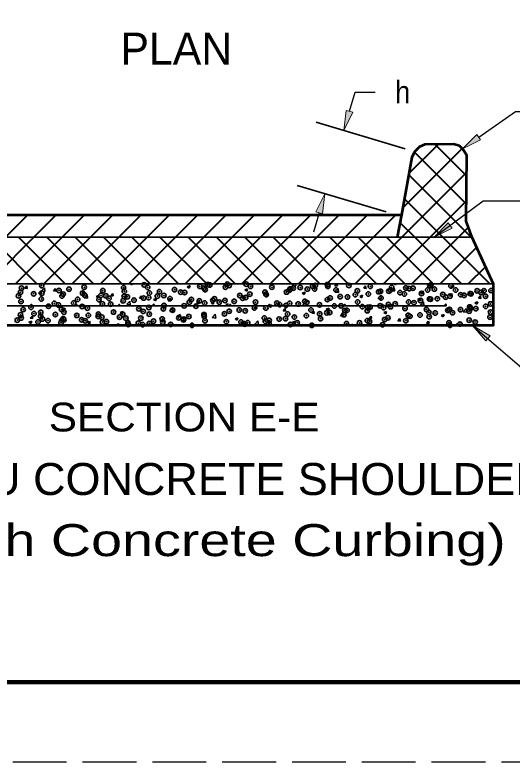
# Model space of a CAD drawing. Extents: x 14 to 49.3, y 28 to 50.
# Drawn here: x 19.642 to 22.747, y 28.044 to 32.715 of the extents above; entities that cross this region are included whole.
import ezdxf

# ---------------------------------------------------------------- set-up
doc = ezdxf.new("R2010")
doc.units = 0
doc.header["$LTSCALE"] = 0.056
doc.header["$PDMODE"] = 32
doc.header["$PDSIZE"] = 0.028
doc.linetypes.add('LONG_DASHED', pattern=[7.5, 6, -1.5])
for name, color, linetype, lineweight in [('1', 7, 'Continuous', 35), ('3', 7, 'Continuous', 13), ('6', 7, 'Continuous', 13)]:
    doc.layers.add(name, color=color, linetype=linetype, lineweight=lineweight)

msp = doc.modelspace()

# ---------------------------------------------------------------- hatches: boundary and pattern name
at = {"layer": '1'}
for points in [[(21.7515, 32.10658), (21.71158, 32.1185), (21.69583, 31.99283), (21.69583, 31.99283)], [(21.56208, 31.47158), (21.52217, 31.4835), (21.57783, 31.59733), (21.57783, 31.59733)]]:
    msp.add_hatch(color=256, dxfattribs=at).paths.add_polyline_path(points)
at = {"layer": '3'}
for points in [[(22.55058, 31.93375), (22.52658, 31.96783), (22.43642, 31.87883), (22.43642, 31.87883)], [(22.373, 31.38267), (22.34825, 31.41617), (22.25983, 31.3255), (22.25983, 31.3255)], [(22.58267, 30.67767), (22.60933, 30.70967), (22.49992, 30.77358), (22.49992, 30.77358)]]:
    msp.add_hatch(color=256, dxfattribs=at).paths.add_polyline_path(points)

# ---------------------------------------------------------------- linework, layer by layer
at = {"layer": '1', "lineweight": 25}
for p, q in [((21.7315, 32.11258), (21.76725, 32.23233)), ((21.76725, 32.23233), (21.89225, 32.23233)), ((21.54208, 31.4775), (21.50633, 31.35775))]:
    msp.add_line(p, q, dxfattribs=at)
at = {"layer": '1'}
for p, q in [((22.07942, 31.87833), (21.52333, 32.04425)), ((21.96142, 31.48292), (21.40533, 31.64875)), ((18.97608, 31.3255), (22.03233, 31.3255)), ((22.03233, 31.3255), (22.4955, 31.3255)), ((18.93983, 31.03367), (22.62858, 31.03367)), ((19.70317, 31.00633), (19.71517, 31.02075)), ((19.71808, 31.00508), (19.71517, 31.02075)), ((20.36208, 31.03367), (20.3715, 31.02733)), ((20.3715, 31.02733), (20.37358, 31.03367)), ((20.71833, 31.01567), (20.73583, 31.02242)), ((20.71833, 31.01567), (20.73075, 31.00725)), ((20.73075, 31.00725), (20.73583, 31.02242)), ((21.37417, 31.02517), (21.38225, 31.03367)), ((21.37417, 31.02517), (21.39642, 31.02175)), ((21.39642, 31.02175), (21.395, 31.03367)), ((21.64092, 31.02183), (21.65083, 31.03367)), ((21.64092, 31.02183), (21.65583, 31.0205)), ((21.65583, 31.0205), (21.65342, 31.03367)), ((21.82025, 31.00617), (21.83225, 31.0205)), ((21.83517, 31.00483), (21.83225, 31.0205)), ((22.01008, 31.03367), (22.01867, 31.02783)), ((22.01867, 31.02783), (22.02058, 31.03367)), ((22.3655, 31.01625), (22.383, 31.02292)), ((22.3655, 31.01625), (22.37792, 31.00783)), ((22.378, 31.00783), (22.383, 31.02292)), ((19.70317, 31.00633), (19.71808, 31.00508)), ((19.78975, 30.97508), (19.80725, 30.98183)), ((19.78975, 30.97508), (19.80217, 30.96667)), ((19.80217, 30.96667), (19.80725, 30.98183)), ((19.80642, 30.98858), (19.82592, 31.00883)), ((19.80642, 30.98858), (19.82867, 30.98508)), ((19.82867, 30.98508), (19.82592, 31.00883)), ((19.8825, 30.99067), (19.8945, 31.005)), ((19.8825, 30.99067), (19.89742, 30.98933)), ((19.89742, 30.98933), (19.8945, 31.005)), ((20.06175, 30.975), (20.07383, 30.98933)), ((20.06175, 30.975), (20.07675, 30.97367)), ((20.07675, 30.97367), (20.07383, 30.98933)), ((20.24108, 30.95933), (20.25317, 30.97367)), ((20.256, 30.958), (20.25317, 30.97367)), ((21.07758, 30.99567), (21.09508, 31.00233)), ((21.07758, 30.99567), (21.09008, 30.98725)), ((21.09008, 30.98725), (21.09517, 31.00233)), ((21.43692, 30.97558), (21.45442, 30.98233)), ((21.43692, 30.97558), (21.44933, 30.96725)), ((21.44933, 30.96725), (21.45442, 30.98233)), ((21.641, 30.98383), (21.66042, 31.00408)), ((21.641, 30.98383), (21.66325, 30.98033)), ((21.66325, 30.98033), (21.66042, 31.00408)), ((21.82025, 31.00617), (21.83517, 31.00483)), ((21.99958, 30.9905), (22.01158, 31.00483)), ((21.99958, 30.9905), (22.0145, 30.98917)), ((22.0145, 30.98917), (22.01158, 31.00483)), ((22.17883, 30.97475), (22.19092, 30.98917)), ((22.17883, 30.97475), (22.19383, 30.9735)), ((22.19383, 30.9735), (22.19092, 30.98917)), ((22.35817, 30.95908), (22.37025, 30.97342)), ((22.37317, 30.95775), (22.37025, 30.97342)), ((20.07325, 30.94717), (20.09275, 30.9675)), ((20.07325, 30.94717), (20.0955, 30.94375)), ((20.0955, 30.94375), (20.09275, 30.9675)), ((20.149, 30.95508), (20.1665, 30.96175)), ((20.149, 30.95508), (20.16142, 30.94667)), ((20.16142, 30.94667), (20.1665, 30.96175)), ((20.24108, 30.95933), (20.256, 30.958)), ((20.34008, 30.90583), (20.35958, 30.92608)), ((20.36233, 30.90233), (20.35958, 30.92608)), ((20.42042, 30.94358), (20.43242, 30.958)), ((20.42042, 30.94358), (20.43533, 30.94233)), ((20.43533, 30.94233), (20.4325, 30.958)), ((20.50825, 30.935), (20.52575, 30.94175)), ((20.50825, 30.935), (20.52075, 30.92667)), ((20.52075, 30.92667), (20.52575, 30.94175)), ((20.59975, 30.92792), (20.61175, 30.94225)), ((20.59975, 30.92792), (20.61467, 30.92658)), ((20.61467, 30.92658), (20.61175, 30.94225)), ((20.779, 30.91225), (20.79108, 30.92658)), ((20.794, 30.91092), (20.79108, 30.92658)), ((21.79617, 30.95558), (21.81367, 30.96233)), ((21.79617, 30.95558), (21.80858, 30.94725)), ((21.80858, 30.94725), (21.81367, 30.96233)), ((21.90783, 30.94242), (21.92725, 30.96275)), ((21.90783, 30.94242), (21.93, 30.939)), ((21.93, 30.939), (21.92725, 30.96275)), ((22.1555, 30.93558), (22.173, 30.94233)), ((22.1555, 30.93558), (22.173, 30.94233)), ((22.1555, 30.93558), (22.16792, 30.92717)), ((22.16792, 30.92717), (22.173, 30.94233)), ((22.35817, 30.95908), (22.37308, 30.95775)), ((22.51475, 30.91558), (22.53225, 30.92225)), ((22.52717, 30.90717), (22.53225, 30.92225)), ((22.5375, 30.94342), (22.54958, 30.95775)), ((22.5375, 30.94342), (22.55242, 30.94208)), ((22.55242, 30.94208), (22.54958, 30.95775)), ((18.88533, 30.89658), (22.33242, 30.89658)), ((19.93892, 30.87442), (19.95642, 30.88117)), ((19.95142, 30.866), (19.95642, 30.88117)), ((20.34008, 30.90583), (20.36233, 30.90233)), ((20.60692, 30.86442), (20.62633, 30.88475)), ((20.62908, 30.861), (20.62633, 30.88475)), ((20.779, 30.91225), (20.794, 30.91092)), ((20.86758, 30.915), (20.88508, 30.92175)), ((20.86758, 30.915), (20.88, 30.90667)), ((20.88, 30.90658), (20.88508, 30.92175)), ((20.95833, 30.89658), (20.97042, 30.91092)), ((20.95833, 30.89658), (20.97325, 30.89525)), ((20.97333, 30.89525), (20.97042, 30.91092)), ((21.13767, 30.88083), (21.14975, 30.89525)), ((21.13767, 30.88083), (21.15258, 30.87958)), ((21.15258, 30.87958), (21.14975, 30.89525)), ((21.22683, 30.895), (21.24433, 30.90175)), ((21.22683, 30.895), (21.23925, 30.88658)), ((21.23925, 30.88658), (21.24433, 30.90167)), ((21.317, 30.86517), (21.329, 30.8795)), ((21.33192, 30.86383), (21.329, 30.8795)), ((21.58617, 30.875), (21.60367, 30.88167)), ((21.59858, 30.86658), (21.60367, 30.88167)), ((22.17458, 30.90108), (22.19408, 30.92133)), ((22.17458, 30.90108), (22.19683, 30.89758)), ((22.19683, 30.89758), (22.19408, 30.92133)), ((22.44142, 30.85967), (22.46092, 30.88)), ((22.46367, 30.85625), (22.46092, 30.88)), ((22.51475, 30.91558), (22.52717, 30.90717)), ((19.73783, 30.81833), (19.74992, 30.83267)), ((19.75275, 30.817), (19.74992, 30.83267)), ((19.93892, 30.87442), (19.95142, 30.866)), ((20.29825, 30.85442), (20.31575, 30.86108)), ((20.29825, 30.85442), (20.31067, 30.846)), ((20.31067, 30.846), (20.31575, 30.86108)), ((20.60692, 30.86442), (20.62908, 30.861)), ((20.6575, 30.83442), (20.675, 30.84108)), ((20.6575, 30.83442), (20.66992, 30.826)), ((20.66992, 30.826), (20.675, 30.84108)), ((20.87367, 30.82308), (20.89317, 30.84333)), ((20.89592, 30.81958), (20.89317, 30.84333)), ((21.317, 30.86517), (21.33192, 30.86383)), ((21.49633, 30.8495), (21.50833, 30.86383)), ((21.49633, 30.8495), (21.51125, 30.84817)), ((21.51125, 30.84817), (21.50833, 30.86383)), ((21.58617, 30.875), (21.59858, 30.86658)), ((21.67558, 30.83383), (21.68767, 30.84817)), ((21.67558, 30.83383), (21.69058, 30.8325)), ((21.69058, 30.8325), (21.68767, 30.84817)), ((21.85492, 30.81808), (21.867, 30.8325)), ((21.86983, 30.81683), (21.867, 30.8325)), ((21.94542, 30.85492), (21.96292, 30.86167)), ((21.94542, 30.85492), (21.95783, 30.84658)), ((21.95783, 30.84658), (21.96292, 30.86167)), ((22.30467, 30.83492), (22.32217, 30.84167)), ((22.30467, 30.83492), (22.31717, 30.8265)), ((22.31717, 30.8265), (22.32217, 30.84167)), ((22.44142, 30.85967), (22.46367, 30.85625)), ((19.72892, 30.79383), (19.74642, 30.8005)), ((19.72892, 30.79383), (19.74133, 30.78542)), ((19.73783, 30.81833), (19.75275, 30.817)), ((19.74133, 30.78542), (19.74642, 30.8005)), ((19.74133, 30.78542), (19.74642, 30.8005)), ((19.91717, 30.80267), (19.92917, 30.817)), ((19.91717, 30.80267), (19.93208, 30.80133)), ((19.93208, 30.80133), (19.92917, 30.817)), ((20.0965, 30.78692), (20.1085, 30.80133)), ((20.0965, 30.78692), (20.11142, 30.78567)), ((20.11142, 30.78567), (20.1085, 30.80133)), ((20.27767, 30.77358), (20.28783, 30.78558)), ((20.29008, 30.77358), (20.28783, 30.78558)), ((20.87367, 30.82308), (20.89592, 30.81958)), ((21.01675, 30.81433), (21.03433, 30.82108)), ((21.01675, 30.81433), (21.02925, 30.806)), ((21.02925, 30.806), (21.03433, 30.82108)), ((21.1405, 30.78167), (21.16, 30.802)), ((21.16275, 30.77825), (21.16, 30.802)), ((21.37608, 30.79433), (21.39358, 30.80108)), ((21.37608, 30.79433), (21.3885, 30.78592)), ((21.3885, 30.78592), (21.39358, 30.80108)), ((21.85492, 30.81808), (21.86983, 30.81683)), ((22.03425, 30.80242), (22.04625, 30.81675)), ((22.03425, 30.80242), (22.04917, 30.80108)), ((22.04917, 30.80108), (22.04633, 30.81675)), ((22.21358, 30.78675), (22.22558, 30.80108)), ((22.21358, 30.78675), (22.2285, 30.78542)), ((22.2285, 30.78542), (22.22558, 30.80108)), ((22.2285, 30.78542), (22.22558, 30.80108)), ((22.395, 30.77358), (22.40492, 30.78542)), ((22.40708, 30.77358), (22.40492, 30.78542)), ((20.08817, 30.77375), (20.10567, 30.7805)), ((20.08817, 30.77375), (20.0885, 30.77358)), ((20.10333, 30.77358), (20.10567, 30.7805)), ((21.1405, 30.78167), (21.16275, 30.77825)), ((21.73533, 30.77433), (21.75283, 30.781)), ((21.73533, 30.77433), (21.7365, 30.77358)), ((21.75033, 30.77358), (21.75283, 30.781))]:
    msp.add_line(p, q, dxfattribs=at)
at = {"layer": '1', "lineweight": 40}
for p, q in [((22.10467, 31.72517), (22.287, 31.9075)), ((22.46117, 31.71025), (22.26408, 31.90725)), ((22.06567, 31.50933), (22.43575, 31.87942)), ((22.45975, 31.53483), (22.13758, 31.857)), ((22.0585, 31.3255), (22.46133, 31.72825)), ((22.49233, 31.3255), (22.10283, 31.715)), ((22.31558, 31.3255), (22.07575, 31.56533)), ((22.23533, 31.3255), (22.45992, 31.55008)), ((19.58367, 31.3255), (19.72325, 31.465)), ((19.76042, 31.3255), (19.9, 31.465)), ((19.93725, 31.3255), (20.07675, 31.465)), ((20.114, 31.3255), (20.25358, 31.465)), ((20.29075, 31.3255), (20.43033, 31.465)), ((20.46758, 31.3255), (20.60708, 31.465)), ((20.64433, 31.3255), (20.78392, 31.465)), ((20.82108, 31.3255), (20.96067, 31.465)), ((20.99792, 31.3255), (21.13742, 31.465)), ((21.17467, 31.3255), (21.31425, 31.465)), ((21.35142, 31.3255), (21.491, 31.465)), ((21.52817, 31.3255), (21.66775, 31.465)), ((21.705, 31.3255), (21.84458, 31.465)), ((21.88175, 31.3255), (22.02133, 31.465)), ((22.13883, 31.3255), (22.04867, 31.41558)), ((22.41208, 31.3255), (22.47292, 31.38625)), ((19.46858, 31.03367), (19.76042, 31.3255)), ((19.779, 31.03367), (19.48717, 31.3255)), ((19.64542, 31.03367), (19.93725, 31.3255)), ((19.95575, 31.03367), (19.66392, 31.3255)), ((19.82217, 31.03367), (20.114, 31.3255)), ((20.1325, 31.03367), (19.84067, 31.3255)), ((19.99892, 31.03367), (20.29075, 31.3255)), ((20.30933, 31.03367), (20.0175, 31.3255)), ((20.17575, 31.03367), (20.46758, 31.3255)), ((20.48608, 31.03367), (20.19425, 31.3255)), ((20.3525, 31.03367), (20.64433, 31.3255)), ((20.66283, 31.03367), (20.371, 31.3255)), ((20.52925, 31.03367), (20.82108, 31.3255)), ((20.83967, 31.03367), (20.54783, 31.3255)), ((20.70608, 31.03367), (20.99792, 31.3255)), ((21.01642, 31.03367), (20.72458, 31.3255)), ((20.88283, 31.03367), (21.17467, 31.3255)), ((21.19317, 31.03367), (20.90133, 31.3255)), ((21.05958, 31.03367), (21.35142, 31.3255)), ((21.37, 31.03367), (21.07817, 31.3255)), ((21.23642, 31.03367), (21.52817, 31.3255)), ((21.54675, 31.03367), (21.25492, 31.3255)), ((21.41317, 31.03367), (21.705, 31.3255)), ((21.7235, 31.03367), (21.43167, 31.3255)), ((21.58992, 31.03367), (21.88175, 31.3255)), ((21.90033, 31.03367), (21.6085, 31.3255)), ((21.76675, 31.03367), (22.0585, 31.3255)), ((22.07708, 31.03367), (21.78525, 31.3255)), ((21.9435, 31.03367), (22.23533, 31.3255)), ((22.25383, 31.03367), (21.962, 31.3255)), ((22.12025, 31.03367), (22.41208, 31.3255)), ((22.43058, 31.03367), (22.13883, 31.3255)), ((22.60742, 31.03367), (22.31558, 31.3255)), ((22.49817, 31.31967), (22.49233, 31.3255)), ((22.29708, 31.03367), (22.52475, 31.26133)), ((22.47383, 31.03367), (22.58008, 31.13992))]:
    msp.add_line(p, q, dxfattribs=at)
at = {"layer": '1', "lineweight": 53}
for p, q in [((18.95792, 31.465), (22.05758, 31.465)), ((22.03233, 31.3255), (22.05758, 31.465)), ((22.4955, 31.3255), (22.62858, 31.03367))]:
    msp.add_line(p, q, dxfattribs=at)
at = {"layer": '1', "linetype": 'LONG_DASHED', "lineweight": 25}
msp.add_line((49.17658, 28.04392), (13.97658, 28.04392), dxfattribs=at)
at = {"layer": '1', "lineweight": 158}
msp.add_lwpolyline([(49.09325, 49.54392), (49.09325, 28.54392), (16.59325, 28.54392)], dxfattribs=at)
at = {"layer": '1', "lineweight": 13}
for points in [[(21.7515, 32.10658), (21.71158, 32.1185), (21.69583, 31.99283), (21.69583, 31.99283)], [(21.56208, 31.47158), (21.52217, 31.4835), (21.57783, 31.59733), (21.57783, 31.59733)]]:
    msp.add_lwpolyline(points, close=True, dxfattribs=at)
at = {"layer": '1', "lineweight": 53}
for points in [[(22.05758, 31.465), (22.123, 31.82633), (22.13925, 31.8605), (22.17025, 31.893), (22.2045, 31.90667), (22.38392, 31.90842), (22.4165, 31.89817), (22.43933, 31.87592), (22.46217, 31.84), (22.45892, 31.42608), (22.49525, 31.32258)], [(22.62858, 31.03367), (22.62858, 30.77358), (18.92167, 30.77358), (18.90958, 30.86875), (18.88533, 30.88775), (18.88533, 30.93217), (18.90958, 30.9575), (18.92167, 30.99558), (18.93983, 31.03367)]]:
    msp.add_lwpolyline(points, dxfattribs=at)
at = {"layer": '1', "lineweight": 40}
for centre, radius, start, end in [((19.74483, 30.90133), 0.00308, 0, 180), ((19.74483, 30.90133), 0.00308, 180, 0), ((20.02533, 30.90133), 0.00308, 0, 180), ((20.02533, 30.90133), 0.00308, 180, 0), ((20.29208, 30.90133), 0.00308, 0, 180), ((20.29208, 30.90133), 0.00308, 180, 0), ((20.50825, 30.90133), 0.00308, 0, 180), ((20.50825, 30.90133), 0.00308, 180, 0), ((20.76525, 30.90133), 0.00304, 0, 180), ((20.76525, 30.90133), 0.00304, 180, 0), ((20.98558, 30.90133), 0.00308, 0, 180), ((20.98558, 30.90133), 0.00308, 180, 0), ((21.2295, 30.90133), 0.00308, 0, 180), ((21.2295, 30.90133), 0.00308, 180, 0), ((21.445, 30.90133), 0.00304, 0, 180), ((21.445, 30.90133), 0.00304, 180, 0), ((21.70292, 30.90133), 0.00304, 0, 180), ((21.70292, 30.90133), 0.00304, 180, 0), ((21.93675, 30.90133), 0.00308, 0, 180), ((21.93675, 30.90133), 0.00308, 180, 0), ((22.18025, 30.90133), 0.00304, 0, 180), ((22.18025, 30.90133), 0.00304, 180, 0), ((22.33225, 30.90133), 0.00304, 0, 180), ((22.33225, 30.90133), 0.00304, 180, 0)]:
    msp.add_arc(centre, radius, start, end, dxfattribs=at)
at = {"layer": '1'}
for p in [(19.68292, 31.00642), (19.80917, 31.02242), (20.07425, 31.01292), (20.3205, 31.01025), (20.44883, 31.02792), (20.47117, 31.01175), (20.79667, 31.01808), (20.82267, 31.00692), (20.84633, 31.02942), (20.85925, 31.02625), (20.9565, 31.013), (20.96842, 31.03192), (20.97975, 31.02375), (21.08642, 31.03175), (21.11325, 31.01808), (21.24667, 31.0125), (21.36125, 31.00242), (21.38017, 31.00683), (21.42383, 31.01067), (21.50133, 31.0195), (21.5185, 31.02317), (21.59433, 31.02917), (21.59617, 31.0185), (21.72783, 31.0235), (21.86125, 31.01783), (21.99475, 31.01225), (22.08308, 31.0075), (22.10392, 31.00358), (22.12817, 31.00658), (22.23375, 31.02233), (22.24092, 31.02833), (22.36575, 31.0205), (19.66442, 30.95892), (19.67625, 30.981), (19.75908, 30.97142), (19.80967, 30.97533), (19.917, 30.99217), (19.936, 30.95792), (19.94317, 30.96975), (19.97958, 31.00042), (20.06433, 30.9755), (20.07658, 30.96408), (20.17958, 30.96167), (20.19058, 30.9915), (20.21008, 30.95842), (20.32367, 30.95575), (20.32533, 30.98675), (20.48158, 30.97658), (20.53108, 30.95683), (20.54417, 30.98483), (20.57208, 30.96067), (20.63883, 30.99725), (20.67683, 30.98183), (20.70192, 30.97942), (20.83025, 30.997), (21.04608, 30.96092), (21.10867, 30.96917), (21.20333, 30.98167), (21.20975, 30.9695), (21.21167, 30.96617), (21.338, 30.98217), (21.3555, 30.9945), (21.46783, 31.00092), (21.51358, 31.00117), (21.64708, 30.99558), (21.76792, 30.966), (21.7805, 30.98992), (21.84925, 30.97), (21.914, 30.98425), (21.92575, 30.98683), (21.97767, 30.98758), (21.98833, 30.99508), (22.04742, 30.97867), (22.07417, 30.97042), (22.18092, 30.973), (22.22, 30.9955), (22.26167, 31.00092), (22.31433, 30.96733), (22.35908, 30.95675), (22.39508, 30.99533), (22.42567, 30.96558), (22.44783, 30.96175), (22.48533, 30.97275), (22.49033, 30.97117), (22.5285, 30.98967), (22.55292, 30.97942), (22.5715, 30.99067), (22.58125, 30.95608), (22.61517, 30.9915), (19.67983, 30.92317), (19.80617, 30.93917), (19.88792, 30.91167), (20.0085, 30.91425), (20.03375, 30.93667), (20.16642, 30.93508), (20.18758, 30.90833), (20.229, 30.94333), (20.31742, 30.92708), (20.3435, 30.95283), (20.38525, 30.93183), (20.44575, 30.94467), (20.477, 30.94717), (20.61042, 30.9415), (20.73092, 30.91942), (20.74392, 30.93592), (20.7935, 30.92767), (20.82725, 30.91375), (20.87733, 30.93025), (20.88817, 30.94017), (20.91808, 30.91942), (20.9535, 30.92983), (21.01075, 30.92458), (21.06392, 30.94442), (21.08333, 30.9485), (21.14425, 30.919), (21.27767, 30.91333), (21.35808, 30.91208), (21.45275, 30.9245), (21.46475, 30.91767), (21.59317, 30.93525), (21.61067, 30.94533), (21.67325, 30.95358), (21.71942, 30.95125), (21.78258, 30.92042), (21.92833, 30.94542), (22.01725, 30.90892), (22.10083, 30.92042), (22.13408, 30.91558), (22.17517, 30.92967), (22.23075, 30.93917), (22.23775, 30.93792), (22.27983, 30.94058), (22.33242, 30.95042), (22.61217, 30.90825), (19.69333, 30.87275), (19.74217, 30.88658), (19.85125, 30.89358), (19.91383, 30.90183), (19.93292, 30.87467), (20.06133, 30.89233), (20.09367, 30.88175), (20.23942, 30.90683), (20.41575, 30.87792), (20.44275, 30.86142), (20.47833, 30.88617), (20.569, 30.87742), (20.57308, 30.89867), (20.6265, 30.86933), (20.69883, 30.89617), (20.77233, 30.89442), (20.98033, 30.86233), (21.04292, 30.87058), (21.08033, 30.86533), (21.13758, 30.883), (21.20867, 30.88292), (21.2955, 30.90383), (21.33492, 30.89892), (21.41117, 30.90767), (21.491, 30.87033), (21.54458, 30.90208), (21.63675, 30.89542), (21.67808, 30.89642), (21.70217, 30.86742), (21.71642, 30.86808), (21.8115, 30.89075), (21.8425, 30.8655), (21.84625, 30.88683), (21.86, 30.88817), (21.92258, 30.89642), (21.945, 30.88517), (21.97458, 30.90442), (21.98825, 30.8905), (22.07842, 30.8795), (22.21192, 30.87383), (22.34533, 30.86825), (22.356, 30.8735), (22.42458, 30.87258), (22.47883, 30.86258), (22.48233, 30.8895), (22.48717, 30.88083), (22.52117, 30.87817), (22.58183, 30.89325), (19.67683, 30.83992), (19.68025, 30.81967), (19.761, 30.84758), (19.80208, 30.83175), (19.80308, 30.856), (19.8945, 30.842), (19.94275, 30.81567), (19.94783, 30.85675), (20.02792, 30.83633), (20.10058, 30.8365), (20.16133, 30.83067), (20.16317, 30.84467), (20.1845, 30.82508), (20.25792, 30.85717), (20.29483, 30.82508), (20.31442, 30.84383), (20.33492, 30.81933), (20.42825, 30.81942), (20.48075, 30.84433), (20.66517, 30.82083), (20.72775, 30.82908), (20.82242, 30.84158), (20.82417, 30.83058), (20.95042, 30.84658), (21.19942, 30.82033), (21.33192, 30.81567), (21.34517, 30.84533), (21.387, 30.82592), (21.46175, 30.83442), (21.54483, 30.84675), (21.55092, 30.8155), (21.59008, 30.85208), (21.60742, 30.85492), (21.69667, 30.8405), (21.97158, 30.82117), (22.09783, 30.83717), (22.10942, 30.83108), (22.172, 30.83933), (22.22767, 30.85592), (22.22958, 30.82808), (22.26667, 30.85183), (22.37533, 30.85308), (22.60908, 30.82508), (22.61225, 30.85692), (19.65625, 30.80667), (19.7855, 30.795), (19.81375, 30.814), (19.84808, 30.80325), (19.92992, 30.7915), (19.94717, 30.80842), (20.05825, 30.80908), (20.08067, 30.80275), (20.18917, 30.79425), (20.21408, 30.79708), (20.3475, 30.7915), (20.35, 30.77933), (20.41258, 30.78758), (20.43967, 30.77825), (20.481, 30.78583), (20.50725, 30.80008), (20.56175, 30.81375), (20.566, 30.79425), (20.61442, 30.78017), (20.69517, 30.80817), (20.69583, 30.813), (20.74792, 30.77458), (20.82867, 30.8025), (20.96208, 30.79683), (21.05358, 30.79525), (21.07183, 30.78442), (21.07725, 30.78208), (21.09558, 30.79125), (21.20558, 30.79967), (21.229, 30.78558), (21.22975, 30.80525), (21.29233, 30.8135), (21.3625, 30.77992), (21.40508, 30.79042), (21.49592, 30.77433), (21.71333, 30.78483), (21.79425, 30.78958), (21.84317, 30.80358), (21.85683, 30.79783), (21.93792, 30.778), (21.9515, 30.81033), (22.08375, 30.80308), (22.353, 30.79033), (22.35883, 30.774), (22.42142, 30.78225), (22.47925, 30.80633), (22.51608, 30.79467)]:
    msp.add_point(p, dxfattribs=at)
at = {"layer": '3', "lineweight": 25}
for points in [[(22.53858, 31.95075), (22.76783, 32.11225), (23.00975, 32.11225)], [(22.25983, 31.3255), (22.56683, 31.55275), (23.04583, 31.55275)], [(22.49992, 30.77358), (22.92508, 30.40925), (23.13925, 30.40925)]]:
    msp.add_lwpolyline(points, dxfattribs=at)
at = {"layer": '3'}
for points in [[(22.55058, 31.93375), (22.52658, 31.96783), (22.43642, 31.87883), (22.43642, 31.87883)], [(22.373, 31.38267), (22.34825, 31.41617), (22.25983, 31.3255), (22.25983, 31.3255)], [(22.58267, 30.67767), (22.60933, 30.70967), (22.49992, 30.77358), (22.49992, 30.77358)]]:
    msp.add_lwpolyline(points, close=True, dxfattribs=at)
at = {"layer": '6'}
for p, q in [((21.69583, 31.99283), (21.69592, 31.99283)), ((22.13925, 31.8605), (22.13933, 31.8605)), ((22.02133, 31.465), (22.02142, 31.465))]:
    msp.add_line(p, q, dxfattribs=at)

# ---------------------------------------------------------------- texts
at = {"layer": '1', "width": 0.9}
msp.add_text('h', height=0.14, dxfattribs=at).set_placement((22.01725, 32.16233))
at = {"layer": '3'}
msp.add_text('PLAN', height=0.2, dxfattribs=at).set_placement((20.3005, 32.40408))
for s, height, width, p in [('SECTION E-E', 0.18, 1.1, (19.85283, 30.11092)), ('JOINT THRU CONCRETE SHOULDER', 0.2, 1.05, (18.00775, 29.71358)), ('(With Concrete Curbing)', 0.2, 1.3, (18.95858, 29.3315))]:
    msp.add_text(s, height=height, dxfattribs=dict(at, width=width)).set_placement(p)

doc.saveas('drawing.dxf')
